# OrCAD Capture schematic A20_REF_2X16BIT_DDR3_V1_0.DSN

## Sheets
1 P01: CPU1: size A3; title: MID; rev: CPU1; note: AllWinner Technology Co.,Ltd
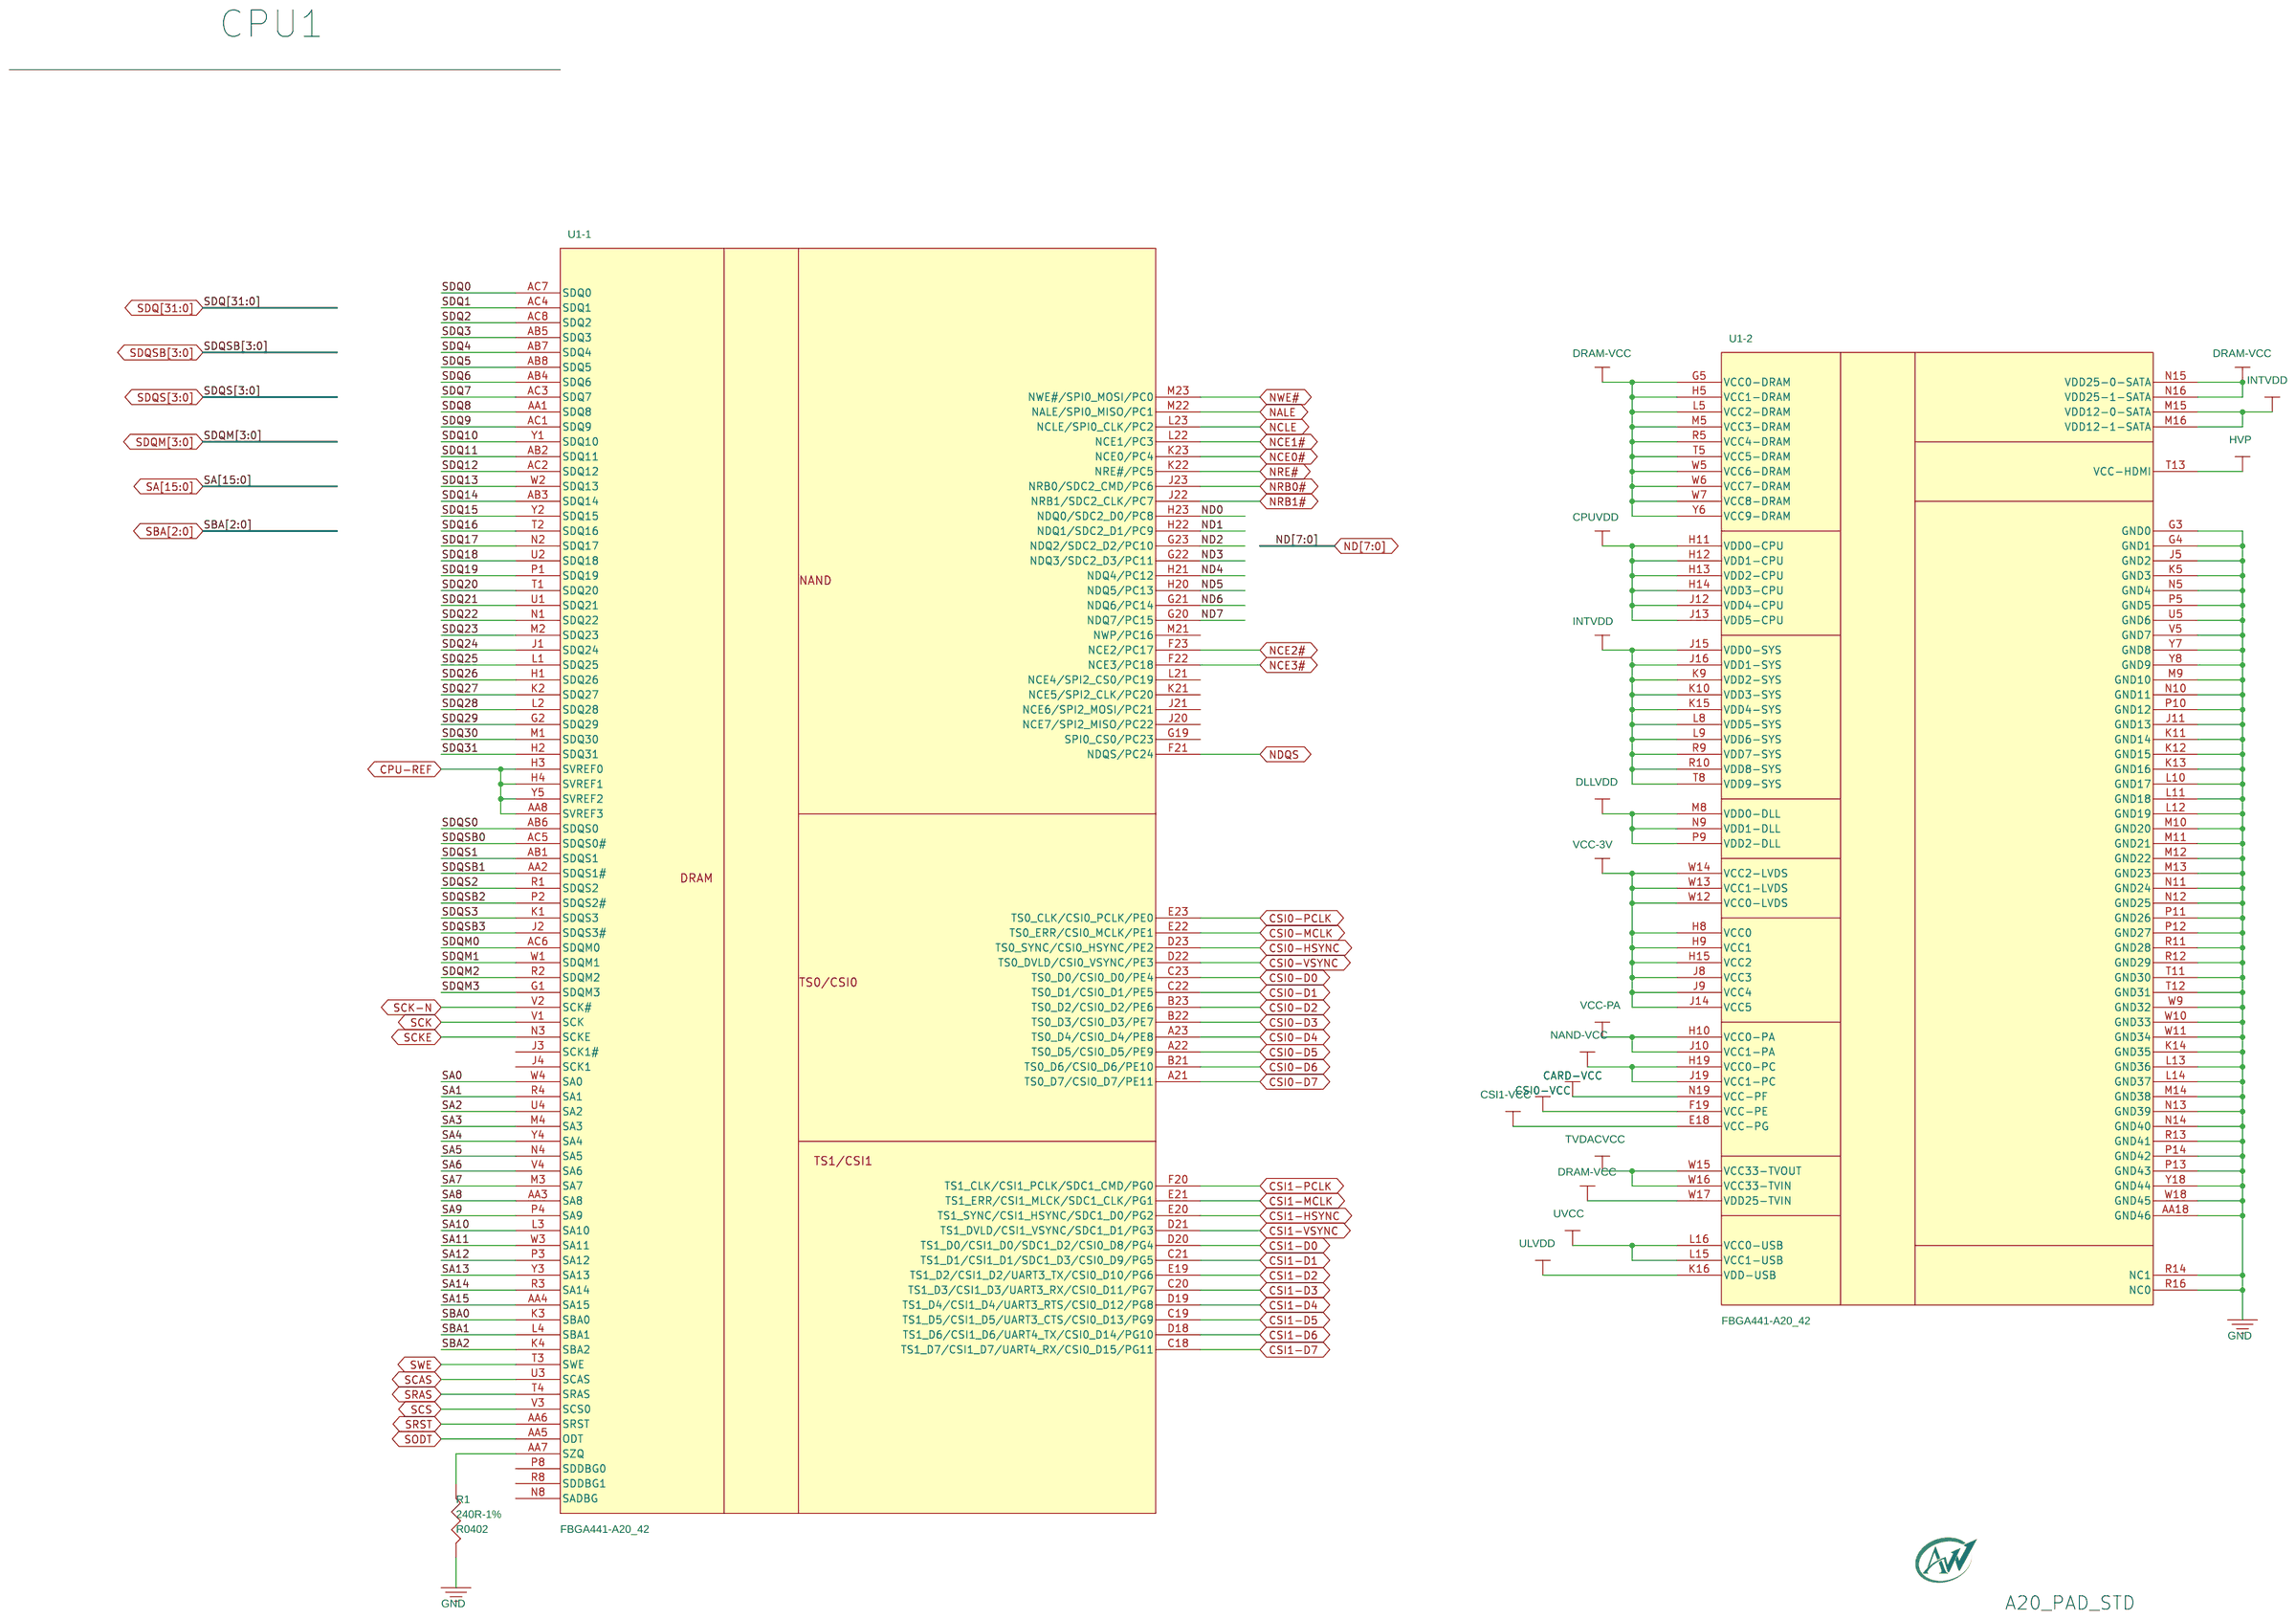
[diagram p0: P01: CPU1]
2 P02: DDR3 16bit x 2pcs: size A3; rev: DDR3 16bit x 2pcs
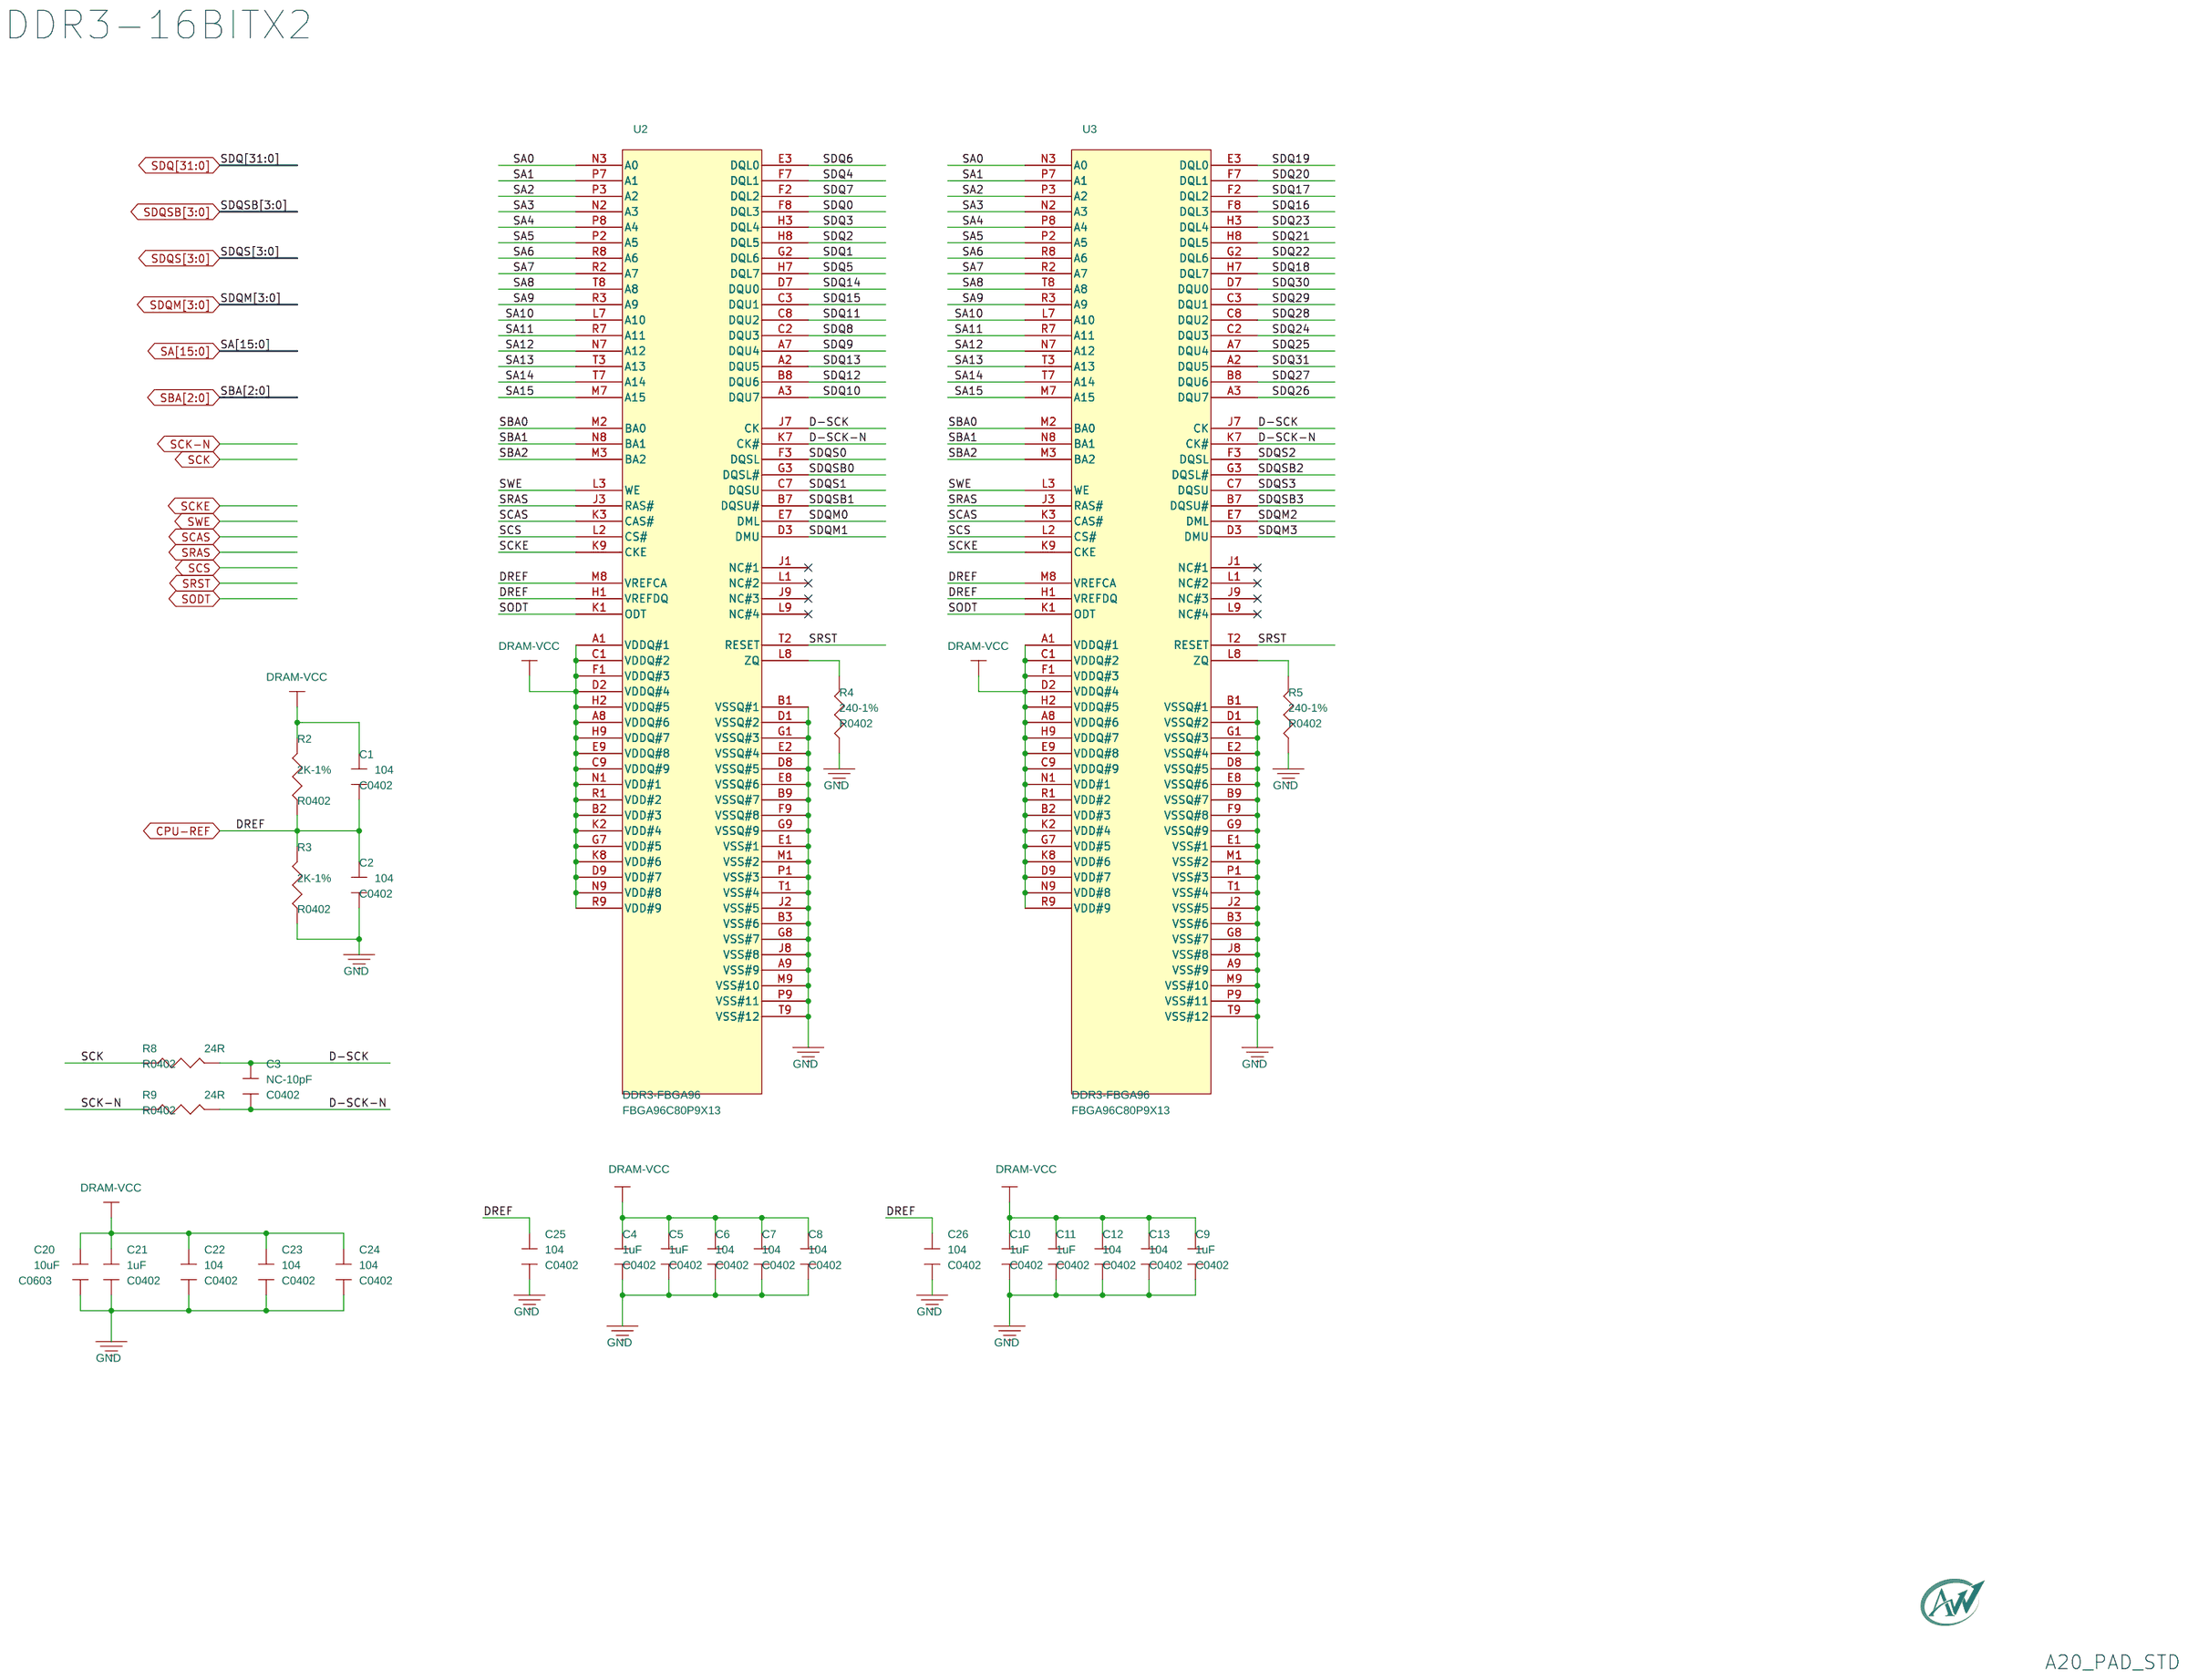
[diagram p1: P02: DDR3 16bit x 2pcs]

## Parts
sheet P01: CPU1
R1  240R-1%  [R0402]
U1  FBGA441-A20_42  [FBGA441C80P19X19]  (sections -1,-2)
sheet P02: DDR3 16bit x 2pcs
C1  104  [C0402]
C2  104  [C0402]
C3  NC-10pF  [C0402]
C4  1uF  [C0402]
C5  1uF  [C0402]
C6  104  [C0402]
C7  104  [C0402]
C8  104  [C0402]
C9  1uF  [C0402]
C10  1uF  [C0402]
C11  1uF  [C0402]
C12  104  [C0402]
C13  104  [C0402]
C20  10uF  [C0603]
C21  1uF  [C0402]
C22  104  [C0402]
C23  104  [C0402]
C24  104  [C0402]
C25  104  [C0402]
C26  104  [C0402]
R2  2K-1%  [R0402]
R3  2K-1%  [R0402]
R4  240-1%  [R0402]
R5  240-1%  [R0402]
R8  24R  [R0402]
R9  24R  [R0402]
U2  DDR3-FBGA96  [FBGA96C80P9X13]
U3  DDR3-FBGA96  [FBGA96C80P9X13]

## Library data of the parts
R1 R4 R5 = R
U1 = FBGA441-A20_42: Color: Default; Location X-Coordinate: 0; Location Y-Coordinate: 0; Power Pins Visible: False; Primitive: DEFAULT; SPLIT_INST: TRUE; SWAP_INFO: (S1+S2+S3+S4)
C1 C2 = CAPACITOR_0: PAGE: 1
C3-C13 C20-C26 = CAPACITOR_0: PAGE: 2
R2 R3 = ?_0
R8 R9 = R1_0805
U2 U3 = DDR3_0

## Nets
GND: C2.1 C4.1 C5.1 C6.1 C7.1 C8.1 C9.1 C10.1 C11.1 C12.1 C13.1 C20.1 C21.1 C22.1 C23.1 C24.1 C25.1 C26.1 R1.2 R3.1 R4.1 R5.1 U1.AA18(GND46) U1.G3(GND0) U1.G4(GND1) U1.J5(GND2) U1.J11(GND13) U1.K5(GND3) U1.K11(GND14) U1.K12(GND15) U1.K13(GND16) U1.K14(GND35) U1.L10(GND17) U1.L11(GND18) U1.L12(GND19) U1.L13(GND36) U1.L14(GND37) U1.M9(GND10) U1.M10(GND20) U1.M11(GND21) U1.M12(GND22) U1.M13(GND23) U1.M14(GND38) U1.N5(GND4) U1.N10(GND11) U1.N11(GND24) U1.N12(GND25) U1.N13(GND39) U1.N14(GND40) U1.P5(GND5) U1.P10(GND12) U1.P11(GND26) U1.P12(GND27) U1.P13(GND43) U1.P14(GND42) U1.R11(GND28) U1.R12(GND29) U1.R13(GND41) U1.R14(NC1) U1.R16(NC0) U1.T11(GND30) U1.T12(GND31) U1.U5(GND6) U1.V5(GND7) U1.W9(GND32) U1.W10(GND33) U1.W11(GND34) U1.W18(GND45) U1.Y7(GND8) U1.Y8(GND9) U1.Y18(GND44) U2.A9(VSS#9) U2.B1(VSSQ#1) U2.B3(VSS#6) U2.B9(VSSQ#7) U2.D1(VSSQ#2) U2.D8(VSSQ#5) U2.E1(VSS#1) U2.E2(VSSQ#4) U2.E8(VSSQ#6) U2.F9(VSSQ#8) U2.G1(VSSQ#3) U2.G8(VSS#7) U2.G9(VSSQ#9) U2.J2(VSS#5) U2.J8(VSS#8) U2.M1(VSS#2) U2.M9(VSS#10) U2.P1(VSS#3) U2.P9(VSS#11) U2.T1(VSS#4) U2.T9(VSS#12) U3.A9(VSS#9) U3.B1(VSSQ#1) U3.B3(VSS#6) U3.B9(VSSQ#7) U3.D1(VSSQ#2) U3.D8(VSSQ#5) U3.E1(VSS#1) U3.E2(VSSQ#4) U3.E8(VSSQ#6) U3.F9(VSSQ#8) U3.G1(VSSQ#3) U3.G8(VSS#7) U3.G9(VSSQ#9) U3.J2(VSS#5) U3.J8(VSS#8) U3.M1(VSS#2) U3.M9(VSS#10) U3.P1(VSS#3) U3.P9(VSS#11) U3.T1(VSS#4) U3.T9(VSS#12)
VCC-3V: U1.H8(VCC0) U1.H9(VCC1) U1.H15(VCC2) U1.J8(VCC3) U1.J9(VCC4) U1.J14(VCC5) U1.W12(VCC0-LVDS) U1.W13(VCC1-LVDS) U1.W14(VCC2-LVDS)
VCC-PA: U1.H10(VCC0-PA) U1.J10(VCC1-PA)
CARD-VCC: U1.N19(VCC-PF)
CPU-REF: C1.1 C2.2 C25.2 C26.2 R2.1 R3.2 U1.AA8(SVREF3) U1.H3(SVREF0) U1.H4(SVREF1) U1.Y5(SVREF2) U2.H1(VREFDQ) U2.M8(VREFCA) U3.H1(VREFDQ) U3.M8(VREFCA)
CPUVDD: U1.H11(VDD0-CPU) U1.H12(VDD1-CPU) U1.H13(VDD2-CPU) U1.H14(VDD3-CPU) U1.J12(VDD4-CPU) U1.J13(VDD5-CPU)
CSI0-D0: U1.C23(TS0_D0/CSI0_D0/PE4)
CSI0-D1: U1.C22(TS0_D1/CSI0_D1/PE5)
CSI0-D2: U1.B23(TS0_D2/CSI0_D2/PE6)
CSI0-D3: U1.B22(TS0_D3/CSI0_D3/PE7)
CSI0-D4: U1.A23(TS0_D4/CSI0_D4/PE8)
CSI0-D5: U1.A22(TS0_D5/CSI0_D5/PE9)
CSI0-D6: U1.B21(TS0_D6/CSI0_D6/PE10)
CSI0-D7: U1.A21(TS0_D7/CSI0_D7/PE11)
CSI0-HSYNC: U1.D23(TS0_SYNC/CSI0_HSYNC/PE2)
CSI0-MCLK: U1.E22(TS0_ERR/CSI0_MCLK/PE1)
CSI0-PCLK: U1.E23(TS0_CLK/CSI0_PCLK/PE0)
CSI0-VCC: U1.F19(VCC-PE)
CSI0-VSYNC: U1.D22(TS0_DVLD/CSI0_VSYNC/PE3)
CSI1-D0: U1.D20(TS1_D0/CSI1_D0/SDC1_D2/CSI0_D8/PG4)
CSI1-D1: U1.C21(TS1_D1/CSI1_D1/SDC1_D3/CSI0_D9/PG5)
CSI1-D2: U1.E19(TS1_D2/CSI1_D2/UART3_TX/CSI0_D10/PG6)
CSI1-D3: U1.C20(TS1_D3/CSI1_D3/UART3_RX/CSI0_D11/PG7)
CSI1-D4: U1.D19(TS1_D4/CSI1_D4/UART3_RTS/CSI0_D12/PG8)
CSI1-D5: U1.C19(TS1_D5/CSI1_D5/UART3_CTS/CSI0_D13/PG9)
CSI1-D6: U1.D18(TS1_D6/CSI1_D6/UART4_TX/CSI0_D14/PG10)
CSI1-D7: U1.C18(TS1_D7/CSI1_D7/UART4_RX/CSI0_D15/PG11)
CSI1-HSYNC: U1.E20(TS1_SYNC/CSI1_HSYNC/SDC1_D0/PG2)
CSI1-MCLK: U1.E21(TS1_ERR/CSI1_MLCK/SDC1_CLK/PG1)
CSI1-PCLK: U1.F20(TS1_CLK/CSI1_PCLK/SDC1_CMD/PG0)
CSI1-VCC: U1.E18(VCC-PG)
CSI1-VSYNC: U1.D21(TS1_DVLD/CSI1_VSYNC/SDC1_D1/PG3)
D-SCK: C3.2 R8.2 U2.J7(CK) U3.J7(CK)
D-SCK-N: C3.1 R9.2 U2.K7(CK#) U3.K7(CK#)
DLLVDD: U1.M8(VDD0-DLL) U1.N9(VDD1-DLL) U1.P9(VDD2-DLL)
DRAM-VCC: C1.2 C4.2 C5.2 C6.2 C7.2 C8.2 C9.2 C10.2 C11.2 C12.2 C13.2 C20.2 C21.2 C22.2 C23.2 C24.2 R2.2 U1.G5(VCC0-DRAM) U1.H5(VCC1-DRAM) U1.L5(VCC2-DRAM) U1.M5(VCC3-DRAM) U1.N15(VDD25-0-SATA) U1.N16(VDD25-1-SATA) U1.R5(VCC4-DRAM) U1.T5(VCC5-DRAM) U1.W5(VCC6-DRAM) U1.W6(VCC7-DRAM) U1.W7(VCC8-DRAM) U1.W17(VDD25-TVIN) U1.Y6(VCC9-DRAM) U2.A1(VDDQ#1) U2.A8(VDDQ#6) U2.B2(VDD#3) U2.C1(VDDQ#2) U2.C9(VDDQ#9) U2.D2(VDDQ#4) U2.D9(VDD#7) U2.E9(VDDQ#8) U2.F1(VDDQ#3) U2.G7(VDD#5) U2.H2(VDDQ#5) U2.H9(VDDQ#7) U2.K2(VDD#4) U2.K8(VDD#6) U2.N1(VDD#1) U2.N9(VDD#8) U2.R1(VDD#2) U2.R9(VDD#9) U3.A1(VDDQ#1) U3.A8(VDDQ#6) U3.B2(VDD#3) U3.C1(VDDQ#2) U3.C9(VDDQ#9) U3.D2(VDDQ#4) U3.D9(VDD#7) U3.E9(VDDQ#8) U3.F1(VDDQ#3) U3.G7(VDD#5) U3.H2(VDDQ#5) U3.H9(VDDQ#7) U3.K2(VDD#4) U3.K8(VDD#6) U3.N1(VDD#1) U3.N9(VDD#8) U3.R1(VDD#2) U3.R9(VDD#9)
HVP: U1.T13(VCC-HDMI)
INTVDD: U1.J15(VDD0-SYS) U1.J16(VDD1-SYS) U1.K9(VDD2-SYS) U1.K10(VDD3-SYS) U1.K15(VDD4-SYS) U1.L8(VDD5-SYS) U1.L9(VDD6-SYS) U1.M15(VDD12-0-SATA) U1.M16(VDD12-1-SATA) U1.R9(VDD7-SYS) U1.R10(VDD8-SYS) U1.T8(VDD9-SYS)
NALE: U1.M22(NALE/SPI0_MISO/PC1)
NAND-VCC: U1.H19(VCC0-PC) U1.J19(VCC1-PC)
NCE0#: U1.K23(NCE0/PC4)
NCE1#: U1.L22(NCE1/PC3)
NCE2#: U1.F23(NCE2/PC17)
NCE3#: U1.F22(NCE3/PC18)
NCLE: U1.L23(NCLE/SPI0_CLK/PC2)
ND0: U1.H23(NDQ0/SDC2_D0/PC8)
ND1: U1.H22(NDQ1/SDC2_D1/PC9)
ND2: U1.G23(NDQ2/SDC2_D2/PC10)
ND3: U1.G22(NDQ3/SDC2_D3/PC11)
ND4: U1.H21(NDQ4/PC12)
ND5: U1.H20(NDQ5/PC13)
ND6: U1.G21(NDQ6/PC14)
ND7: U1.G20(NDQ7/PC15)
NDQS: U1.F21(NDQS/PC24)
NRB0#: U1.J23(NRB0/SDC2_CMD/PC6)
NRB1#: U1.J22(NRB1/SDC2_CLK/PC7)
NRE#: U1.K22(NRE#/PC5)
NWE#: U1.M23(NWE#/SPI0_MOSI/PC0)
SA0: U1.W4(SA0) U2.N3(A0) U3.N3(A0)
SA1: U1.R4(SA1) U2.P7(A1) U3.P7(A1)
SA2: U1.U4(SA2) U2.P3(A2) U3.P3(A2)
SA3: U1.M4(SA3) U2.N2(A3) U3.N2(A3)
SA4: U1.Y4(SA4) U2.P8(A4) U3.P8(A4)
SA5: U1.N4(SA5) U2.P2(A5) U3.P2(A5)
SA6: U1.V4(SA6) U2.R8(A6) U3.R8(A6)
SA7: U1.M3(SA7) U2.R2(A7) U3.R2(A7)
SA8: U1.AA3(SA8) U2.T8(A8) U3.T8(A8)
SA9: U1.P4(SA9) U2.R3(A9) U3.R3(A9)
SA10: U1.L3(SA10) U2.L7(A10) U3.L7(A10)
SA11: U1.W3(SA11) U2.R7(A11) U3.R7(A11)
SA12: U1.P3(SA12) U2.N7(A12) U3.N7(A12)
SA13: U1.Y3(SA13) U2.T3(A13) U3.T3(A13)
SA14: U1.R3(SA14) U2.T7(A14) U3.T7(A14)
SA15: U1.AA4(SA15) U2.M7(A15) U3.M7(A15)
SBA0: U1.K3(SBA0) U2.M2(BA0) U3.M2(BA0)
SBA1: U1.L4(SBA1) U2.N8(BA1) U3.N8(BA1)
SBA2: U1.K4(SBA2) U2.M3(BA2) U3.M3(BA2)
SCAS: U1.U3(SCAS) U2.K3(CAS#) U3.K3(CAS#)
SCK: R8.1 U1.V1(SCK)
SCK-N: R9.1 U1.V2(SCK#)
SCKE: U1.N3(SCKE) U2.K9(CKE) U3.K9(CKE)
SCS: U1.V3(SCS0) U2.L2(CS#) U3.L2(CS#)
SDQ0: U1.AC7(SDQ0) U2.F8(DQL3)
SDQ1: U1.AC4(SDQ1) U2.G2(DQL6)
SDQ2: U1.AC8(SDQ2) U2.H8(DQL5)
SDQ3: U1.AB5(SDQ3) U2.H3(DQL4)
SDQ4: U1.AB7(SDQ4) U2.F7(DQL1)
SDQ5: U1.AB8(SDQ5) U2.H7(DQL7)
SDQ6: U1.AB4(SDQ6) U2.E3(DQL0)
SDQ7: U1.AC3(SDQ7) U2.F2(DQL2)
SDQ8: U1.AA1(SDQ8) U2.C2(DQU3)
SDQ9: U1.AC1(SDQ9) U2.A7(DQU4)
SDQ10: U1.Y1(SDQ10) U2.A3(DQU7)
SDQ11: U1.AB2(SDQ11) U2.C8(DQU2)
SDQ12: U1.AC2(SDQ12) U2.B8(DQU6)
SDQ13: U1.W2(SDQ13) U2.A2(DQU5)
SDQ14: U1.AB3(SDQ14) U2.D7(DQU0)
SDQ15: U1.Y2(SDQ15) U2.C3(DQU1)
SDQ16: U1.T2(SDQ16) U3.F8(DQL3)
SDQ17: U1.N2(SDQ17) U3.F2(DQL2)
SDQ18: U1.U2(SDQ18) U3.H7(DQL7)
SDQ19: U1.P1(SDQ19) U3.E3(DQL0)
SDQ20: U1.T1(SDQ20) U3.F7(DQL1)
SDQ21: U1.U1(SDQ21) U3.H8(DQL5)
SDQ22: U1.N1(SDQ22) U3.G2(DQL6)
SDQ23: U1.M2(SDQ23) U3.H3(DQL4)
SDQ24: U1.J1(SDQ24) U3.C2(DQU3)
SDQ25: U1.L1(SDQ25) U3.A7(DQU4)
SDQ26: U1.H1(SDQ26) U3.A3(DQU7)
SDQ27: U1.K2(SDQ27) U3.B8(DQU6)
SDQ28: U1.L2(SDQ28) U3.C8(DQU2)
SDQ29: U1.G2(SDQ29) U3.C3(DQU1)
SDQ30: U1.M1(SDQ30) U3.D7(DQU0)
SDQ31: U1.H2(SDQ31) U3.A2(DQU5)
SDQM0: U1.AC6(SDQM0) U2.E7(DML)
SDQM1: U1.W1(SDQM1) U2.D3(DMU)
SDQM2: U1.R2(SDQM2) U3.E7(DML)
SDQM3: U1.G1(SDQM3) U3.D3(DMU)
SDQS0: U1.AB6(SDQS0) U2.F3(DQSL)
SDQS1: U1.AB1(SDQS1) U2.C7(DQSU)
SDQS2: U1.R1(SDQS2) U3.F3(DQSL)
SDQS3: U1.K1(SDQS3) U3.C7(DQSU)
SDQSB0: U1.AC5(SDQS0#) U2.G3(DQSL#)
SDQSB1: U1.AA2(SDQS1#) U2.B7(DQSU#)
SDQSB2: U1.P2(SDQS2#) U3.G3(DQSL#)
SDQSB3: U1.J2(SDQS3#) U3.B7(DQSU#)
SODT: U1.AA5(ODT) U2.K1(ODT) U3.K1(ODT)
SRAS: U1.T4(SRAS) U2.J3(RAS#) U3.J3(RAS#)
SRST: U1.AA6(SRST) U2.T2(RESET) U3.T2(RESET)
SWE: U1.T3(SWE) U2.L3(WE) U3.L3(WE)
TVDACVCC: U1.W15(VCC33-TVOUT) U1.W16(VCC33-TVIN)
ULVDD: U1.K16(VDD-USB)
UVCC: U1.L15(VCC1-USB) U1.L16(VCC0-USB)
N63143528: R1.1 U1.AA7(SZQ)
N63153971: R4.2 U2.L8(ZQ)
N63154322: R5.2 U3.L8(ZQ)

Not connected (* = marked no-connect by the designer): U1 G19(SPI0_CS0/PC23) J3(SCK1#) J4(SCK1) J20(NCE7/SPI2_MISO/PC22) J21(NCE6/SPI2_MOSI/PC21) K21(NCE5/SPI2_CLK/PC20) L21(NCE4/SPI2_CS0/PC19) M21(NWP/PC16) N8(SADBG) P8(SDDBG0) R8(SDDBG1); U2 J1(NC#1)* J9(NC#3)* L1(NC#2)* L9(NC#4)*; U3 J1(NC#1)* J9(NC#3)* L1(NC#2)* L9(NC#4)*

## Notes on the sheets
sheet 1
- CPU1
- A20_PAD_STD
sheet 2
- DDR3-16BITX2
- A20_PAD_STD
